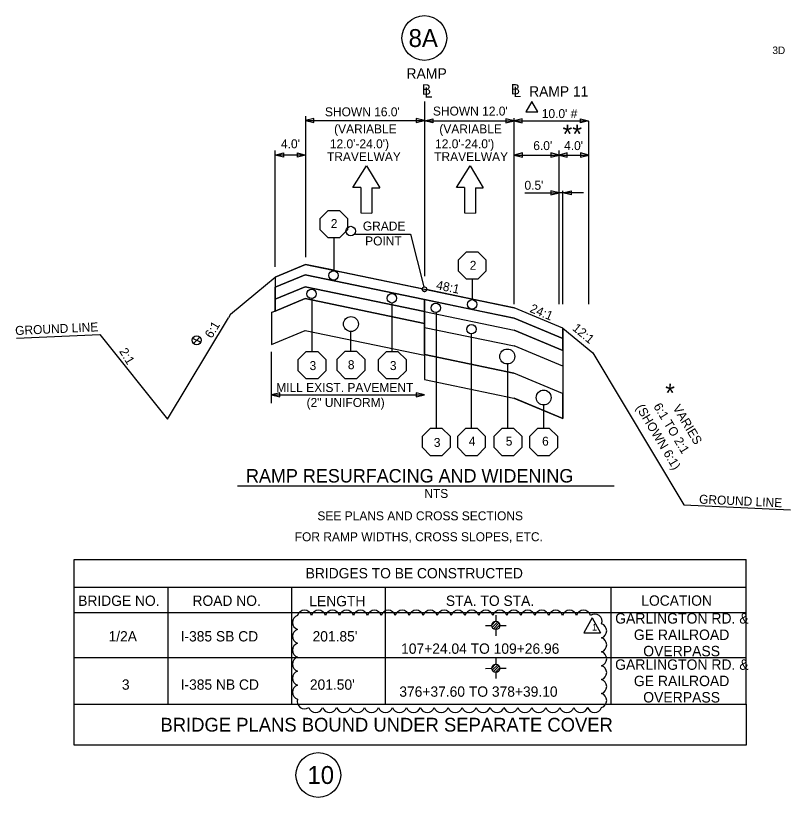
# Model space of a CAD drawing. Extents: x 5017 to 5774, y 4942 to 5266.
# Drawn here: x 5241.9 to 5345.7, y 5114.2 to 5219 of the extents above; entities that cross this region are included whole.
import ezdxf

# ---------------------------------------------------------------- set-up
doc = ezdxf.new("R2010")
doc.units = 0
for name, color, linetype in [('Level 20', 7, 'Continuous'), ('Level 25', 7, 'Continuous'), ('NotForConst', 7, 'Continuous'), ('RD_DDB_EX_Tx', 7, 'Continuous'), ('RD_EX_SU_TX_Misc', 7, 'Continuous'), ('RD_QTY_Intermediate', 7, 'Continuous'), ('RD_QTY_Surf_Course', 7, 'Continuous'), ('RD_SHT_TX', 7, 'Continuous'), ('RD_SHT_Typical', 7, 'Continuous'), ('RD_TX_Misc2', 7, 'Continuous'), ('RD_TX_StaOff', 7, 'Continuous'), ('RD_TX_TypSect', 7, 'Continuous'), ('RD_XS_ExGround', 7, 'Continuous'), ('RD_XS_ExPaveRet', 7, 'Continuous'), ('typical_on', 7, 'Continuous')]:
    doc.layers.add(name, color=color, linetype=linetype)

# ---------------------------------------------------------------- blocks, each defined once
blk = doc.blocks.new('SUE_TFP')
at = {"layer": 'RD_EX_SU_TX_Misc'}
for p, q in [((0, 5.5), (0, 2.22)), ((-2.21, 0.13), (-0.13, 2.21)), ((-1.96, -1.03), (1.03, 1.96)), ((-1.31, -1.79), (1.79, 1.31)), ((-0.3, -2.2), (2.2, 0.3)), ((2.22, 0), (5.53, 0.01)), ((-5.53, -0.01), (-2.22, 0)), ((0, -2.22), (0, -5.5))]:
    blk.add_line(p, q, dxfattribs=at)
blk.add_circle((0, 0), 2.22, dxfattribs=at)

msp = doc.modelspace()

# ---------------------------------------------------------------- linework, layer by layer
at = {"layer": 'Level 20'}
for p, q in [((5287.11, 5195.94), (5288.93, 5198.86)), ((5288.93, 5198.86), (5290.71, 5195.93)), ((5300.99, 5195.94), (5302.81, 5198.86)), ((5302.81, 5198.86), (5304.59, 5195.93)), ((5288.2, 5195.94), (5287.11, 5195.94)), ((5288.2, 5195.94), (5288.2, 5192.54)), ((5289.66, 5195.93), (5290.71, 5195.93)), ((5289.66, 5195.93), (5289.66, 5192.53)), ((5302.08, 5195.94), (5300.99, 5195.94)), ((5302.08, 5195.94), (5302.08, 5192.54)), ((5303.54, 5195.93), (5304.59, 5195.93)), ((5303.54, 5195.93), (5303.54, 5192.53)), ((5288.2, 5192.54), (5289.66, 5192.53)), ((5302.08, 5192.54), (5303.54, 5192.53))]:
    msp.add_line(p, q, dxfattribs=at)
at = {"layer": 'Level 25'}
msp.add_lwpolyline([(5287.46, 5189.7), (5294.82, 5189.7), (5296.63, 5182.62)], dxfattribs=at)
for centre in [(5296.69, 5215.99), (5282.48, 5117.2)]:
    msp.add_circle(centre, 3, dxfattribs=at)
at = {"layer": 'NotForConst'}
for p, q in [((5249.76, 5126.71), (5249.76, 5146.1)), ((5249.76, 5146.1), (5339.84, 5146.1)), ((5339.84, 5126.71), (5339.84, 5146.1)), ((5249.76, 5142.4), (5339.84, 5142.4)), ((5278.92, 5126.71), (5278.92, 5142.4)), ((5291.48, 5126.71), (5291.48, 5142.4)), ((5321.75, 5126.71), (5321.75, 5142.4)), ((5249.76, 5138.97), (5339.84, 5138.97)), ((5249.76, 5132.93), (5339.84, 5132.93))]:
    msp.add_line(p, q, dxfattribs=at)
msp.add_lwpolyline([(5249.76, 5126.71), (5339.84, 5126.71), (5339.84, 5121.18), (5249.76, 5121.18)], close=True, dxfattribs=at)
at = {"layer": 'RD_DDB_EX_Tx'}
for p, q in [((5308.68, 5171.06), (5296.71, 5173.55)), ((5315.22, 5168.33), (5308.68, 5171.06)), ((5296.71, 5170.22), (5308.68, 5167.72)), ((5315.25, 5164.99), (5315.25, 5168.33)), ((5308.68, 5167.72), (5315.25, 5164.99))]:
    msp.add_line(p, q, dxfattribs=at)
for points in [[(5296.71, 5173.55), (5296.71, 5171.35), (5296.71, 5170.22)], [(5315.25, 5168.33), (5315.22, 5168.33)]]:
    msp.add_lwpolyline(points, dxfattribs=at)
msp.add_circle((5312.68, 5167.8), 1, dxfattribs=at)
at = {"layer": 'RD_QTY_Intermediate'}
for p, q in [((5280.73, 5184.26), (5276.71, 5182.58)), ((5296.71, 5180.93), (5280.73, 5184.26)), ((5276.71, 5180.98), (5280.73, 5182.66)), ((5280.73, 5182.66), (5276.71, 5180.98)), ((5276.71, 5182.58), (5276.71, 5180.98)), ((5280.73, 5182.66), (5296.71, 5179.33)), ((5296.71, 5179.33), (5280.73, 5182.66)), ((5276.71, 5179.39), (5280.73, 5181.06)), ((5276.71, 5180.98), (5276.71, 5179.39)), ((5280.73, 5181.06), (5296.71, 5177.74)), ((5296.71, 5180.93), (5296.71, 5179.33)), ((5296.71, 5179.33), (5296.71, 5180.93)), ((5296.71, 5179.33), (5308.71, 5176.83)), ((5296.71, 5177.74), (5296.71, 5179.33)), ((5315.23, 5175.71), (5308.71, 5178.43)), ((5308.71, 5176.83), (5315.23, 5174.11)), ((5315.25, 5174.11), (5315.25, 5175.71))]:
    msp.add_line(p, q, dxfattribs=at)
for points in [[(5308.71, 5178.43), (5303.07, 5179.6), (5296.71, 5180.93)], [(5315.25, 5175.71), (5315.23, 5175.71)], [(5315.23, 5174.11), (5315.25, 5174.11)]]:
    msp.add_lwpolyline(points, dxfattribs=at)
at = {"layer": 'RD_QTY_Surf_Course'}
for p, q in [((5280.77, 5185.64), (5276.71, 5183.95)), ((5284.55, 5184.86), (5280.77, 5185.64)), ((5276.71, 5182.58), (5280.73, 5184.26)), ((5280.73, 5184.26), (5296.71, 5180.93)), ((5284.55, 5184.79), (5284.55, 5184.86)), ((5296.41, 5182.39), (5284.56, 5184.85)), ((5276.71, 5183.95), (5276.71, 5182.58)), ((5303.1, 5180.99), (5297, 5182.26)), ((5296.71, 5180.93), (5308.71, 5178.43)), ((5303.1, 5180.92), (5303.1, 5180.99)), ((5308.71, 5179.82), (5303.12, 5180.99)), ((5315.25, 5177.1), (5308.71, 5179.82)), ((5308.71, 5178.43), (5315.23, 5175.71)), ((5315.25, 5175.71), (5315.25, 5177.1))]:
    msp.add_line(p, q, dxfattribs=at)
for points in [[(5284.56, 5184.85), (5284.55, 5184.79)], [(5303.12, 5180.99), (5303.1, 5180.92)], [(5315.23, 5175.71), (5315.25, 5175.71)]]:
    msp.add_lwpolyline(points, dxfattribs=at)
for centre in [(5284.53, 5184.17), (5303.09, 5180.29)]:
    msp.add_circle(centre, 0.63, dxfattribs=at)
msp.add_arc((5296.71, 5182.32), 0.3, 168.2319, 348.2319, dxfattribs=at)
at = {"layer": 'RD_SHT_TX'}
for p, q in [((5319.18, 5138.27), (5318.05, 5136.24)), ((5319.18, 5138.27), (5320.32, 5136.24)), ((5318.05, 5136.24), (5320.32, 5136.24))]:
    msp.add_line(p, q, dxfattribs=at)
for centre, start, end in [((5280.64, 5138.3), 17.5, 162.5), ((5282.51, 5138.3), 17.5, 162.5), ((5284.38, 5138.3), 17.5, 162.5), ((5286.25, 5138.3), 17.5, 162.5), ((5288.12, 5138.3), 17.5, 162.5), ((5289.99, 5138.3), 17.5, 162.5), ((5291.86, 5138.3), 17.5, 162.5), ((5293.73, 5138.3), 17.5, 162.5), ((5295.6, 5138.3), 17.5, 162.5), ((5297.47, 5138.3), 17.5, 162.5), ((5299.34, 5138.3), 17.5, 162.5), ((5301.2, 5138.3), 17.5, 162.5), ((5303.07, 5138.3), 17.5, 162.5), ((5304.94, 5138.3), 17.5, 162.5), ((5306.81, 5138.3), 17.5, 162.5), ((5308.68, 5138.3), 17.5, 162.5), ((5310.55, 5138.3), 17.5, 162.5), ((5312.42, 5138.3), 17.5, 162.5), ((5314.29, 5138.3), 17.5, 162.5), ((5316.16, 5138.3), 17.5, 162.5), ((5318.03, 5138.3), 17.5, 162.5), ((5280, 5137.66), 107.5, 252.5), ((5319.53, 5137.79), 340.297, 125.297), ((5320.15, 5136.53), 287.5, 72.5), ((5280, 5135.79), 107.5, 252.5), ((5280, 5133.92), 107.5, 252.5), ((5320.15, 5134.66), 287.5, 72.5), ((5320.15, 5132.79), 287.5, 72.5), ((5280, 5132.05), 107.5, 252.5), ((5320.15, 5130.92), 287.5, 72.5), ((5280, 5130.18), 107.5, 252.5), ((5320.15, 5129.05), 287.5, 72.5), ((5280, 5128.31), 107.5, 252.5), ((5320.15, 5127.18), 287.5, 72.5), ((5280.63, 5127.05), 160.297, 305.297), ((5282.13, 5126.54), 197.5, 342.5), ((5284, 5126.54), 197.5, 342.5), ((5285.87, 5126.54), 197.5, 342.5), ((5287.74, 5126.54), 197.5, 342.5), ((5289.61, 5126.54), 197.5, 342.5), ((5291.48, 5126.54), 197.5, 342.5), ((5293.35, 5126.54), 197.5, 342.5), ((5295.22, 5126.54), 197.5, 342.5), ((5297.09, 5126.54), 197.5, 342.5), ((5298.95, 5126.54), 197.5, 342.5), ((5300.82, 5126.54), 197.5, 342.5), ((5302.69, 5126.54), 197.5, 342.5), ((5304.56, 5126.54), 197.5, 342.5), ((5306.43, 5126.54), 197.5, 342.5), ((5308.3, 5126.54), 197.5, 342.5), ((5310.17, 5126.54), 197.5, 342.5), ((5312.04, 5126.54), 197.5, 342.5), ((5313.91, 5126.54), 197.5, 342.5), ((5315.78, 5126.54), 197.5, 342.5), ((5317.65, 5126.54), 197.5, 342.5), ((5319.51, 5126.54), 197.5, 342.5)]:
    msp.add_arc(centre, 0.98, start, end, dxfattribs=at)
at = {"layer": 'RD_SHT_Typical'}
for p, q in [((5276.71, 5183.95), (5280.77, 5185.64)), ((5276.71, 5182.58), (5280.73, 5184.26)), ((5276.71, 5183.95), (5276.71, 5182.58)), ((5276.71, 5180.98), (5280.73, 5182.66)), ((5276.71, 5180.98), (5276.71, 5182.58)), ((5276.21, 5179.18), (5280.73, 5181.06)), ((5276.71, 5179.39), (5276.71, 5180.98)), ((5315.25, 5177.1), (5308.71, 5179.82)), ((5276.21, 5179.18), (5276.21, 5174.92)), ((5296.71, 5179.33), (5296.71, 5177.74)), ((5296.71, 5177.74), (5296.71, 5176.36)), ((5296.71, 5173.55), (5296.71, 5177.74)), ((5315.23, 5175.71), (5308.71, 5178.43)), ((5276.21, 5174.92), (5280.73, 5176.8)), ((5315.23, 5174.11), (5308.71, 5176.83)), ((5315.25, 5177.1), (5319.25, 5173.77)), ((5315.25, 5177.1), (5315.25, 5164.99)), ((5296.71, 5176.36), (5296.71, 5173.48)), ((5315.23, 5172), (5308.71, 5174.71)), ((5296.71, 5173.55), (5296.71, 5170.22)), ((5319.25, 5173.77), (5331.47, 5153.4)), ((5315.22, 5168.33), (5308.68, 5171.06)), ((5315.25, 5164.99), (5308.71, 5167.72))]:
    msp.add_line(p, q, dxfattribs=at)
for points in [[(5280.77, 5185.64), (5296.71, 5182.32)], [(5280.73, 5184.26), (5296.71, 5180.93)], [(5280.73, 5182.66), (5296.71, 5179.33)], [(5296.71, 5182.32), (5308.71, 5179.82)], [(5280.73, 5181.06), (5296.71, 5177.74)], [(5296.71, 5180.93), (5308.71, 5178.43)], [(5296.71, 5179.33), (5308.71, 5176.83)], [(5280.73, 5176.8), (5296.71, 5173.48)], [(5296.71, 5177.21), (5308.71, 5174.71)], [(5296.71, 5173.55), (5308.68, 5171.06)], [(5296.71, 5170.22), (5308.68, 5167.72)]]:
    msp.add_lwpolyline(points, dxfattribs=at)
at = {"layer": 'RD_TX_StaOff'}
msp.add_line((5262.31, 5142.4), (5262.31, 5126.71), dxfattribs=at)
at = {"layer": 'RD_TX_TypSect'}
for p, q in [((5296.7, 5207.49), (5296.7, 5184.08)), ((5280.77, 5205.52), (5280.77, 5186.62)), ((5308.71, 5180.31), (5308.71, 5205.24)), ((5280.77, 5204.93), (5296.71, 5204.93)), ((5296.71, 5204.9), (5308.71, 5204.9)), ((5308.71, 5204.9), (5318.71, 5204.9)), ((5318.75, 5180.31), (5318.75, 5204.83)), ((5276.71, 5185.31), (5276.71, 5200.92)), ((5314.75, 5180.31), (5314.75, 5200.92)), ((5280.77, 5200.3), (5276.71, 5200.3)), ((5308.75, 5200.3), (5314.75, 5200.3)), ((5314.75, 5200.3), (5318.75, 5200.3)), ((5310.16, 5195.23), (5314.75, 5195.23)), ((5318.01, 5195.23), (5314.75, 5195.23)), ((5315.25, 5180.31), (5315.25, 5195.5)), ((5284.55, 5189.19), (5284.55, 5184.79)), ((5303.1, 5183.65), (5303.1, 5180.92)), ((5281.65, 5173.99), (5281.65, 5181.06)), ((5292.4, 5173.99), (5292.4, 5180.47)), ((5298.3, 5163.69), (5298.3, 5179.27)), ((5265.64, 5175.74), (5266.72, 5175.2)), ((5265.77, 5175.05), (5266.59, 5175.9)), ((5286.85, 5174.02), (5286.85, 5176.65)), ((5303.02, 5163.69), (5303.02, 5176.35)), ((5276.21, 5167.03), (5276.21, 5173.91)), ((5307.9, 5163.69), (5307.9, 5172.32)), ((5312.69, 5163.69), (5312.69, 5166.8)), ((5271.64, 5155.95), (5322.14, 5155.95))]:
    msp.add_line(p, q, dxfattribs=at)
for points in [[(5311.09, 5207.48), (5310.29, 5206.09), (5311.89, 5206.09)], [(5281.87, 5204.65), (5281.87, 5205.2), (5280.77, 5204.93)], [(5295.6, 5205.2), (5295.6, 5204.65), (5296.71, 5204.93)], [(5297.81, 5205.17), (5297.81, 5204.62), (5296.71, 5204.9)], [(5307.61, 5205.17), (5307.61, 5204.62), (5308.71, 5204.9)], [(5309.81, 5204.62), (5309.81, 5205.17), (5308.71, 5204.9)], [(5317.6, 5204.62), (5317.6, 5205.17), (5318.71, 5204.9)], [(5277.82, 5200.58), (5277.82, 5200.03), (5276.71, 5200.3)], [(5279.67, 5200.03), (5279.67, 5200.58), (5280.77, 5200.3)], [(5309.85, 5200.03), (5309.85, 5200.58), (5308.75, 5200.3)], [(5313.64, 5200.58), (5313.64, 5200.03), (5314.75, 5200.3)], [(5315.85, 5200.03), (5315.85, 5200.58), (5314.75, 5200.3)], [(5317.64, 5200.58), (5317.64, 5200.03), (5318.75, 5200.3)], [(5313.64, 5195.5), (5313.64, 5194.95), (5314.75, 5195.23)], [(5316.35, 5195.5), (5316.35, 5194.95), (5315.25, 5195.23)], [(5277.32, 5167.88), (5277.32, 5168.43), (5276.21, 5168.15)], [(5295.6, 5168.43), (5295.6, 5167.88), (5296.71, 5168.15)]]:
    msp.add_lwpolyline(points, close=True, dxfattribs=at)
for centre, radius in [((5286.82, 5190.12), 0.63), ((5284.53, 5184.17), 0.63), ((5281.58, 5181.69), 0.63), ((5296.71, 5182.32), 0.3), ((5292.34, 5181.1), 0.63), ((5303.09, 5180.29), 0.63), ((5298.23, 5179.82), 0.63), ((5286.85, 5177.65), 1), ((5303, 5176.96), 0.63), ((5266.18, 5175.48), 0.6), ((5307.8, 5173.3), 1), ((5312.68, 5167.8), 1)]:
    msp.add_circle(centre, radius, dxfattribs=at)
at = {"layer": 'RD_XS_ExGround'}
for p, q in [((5274.11, 5181.78), (5276.71, 5183.95)), ((5270.72, 5178.96), (5274.11, 5181.78)), ((5270.72, 5178.96), (5270.45, 5178.47)), ((5262.28, 5164.9), (5270.45, 5178.47)), ((5242.05, 5175.75), (5253.2, 5176.25)), ((5253.2, 5176.25), (5262.28, 5164.9)), ((5276.21, 5168.15), (5296.71, 5168.15)), ((5331.47, 5153.4), (5345.74, 5152.75))]:
    msp.add_line(p, q, dxfattribs=at)
at = {"layer": 'RD_XS_ExPaveRet'}
for p, q in [((5296.71, 5177.74), (5280.73, 5181.06)), ((5276.21, 5179.18), (5276.21, 5174.92)), ((5296.71, 5177.51), (5296.71, 5177.74)), ((5276.21, 5174.92), (5280.73, 5176.8)), ((5280.73, 5176.8), (5296.71, 5173.48))]:
    msp.add_line(p, q, dxfattribs=at)
for points in [[(5280.73, 5181.06), (5276.71, 5179.39), (5276.21, 5179.18)], [(5296.71, 5173.48), (5296.71, 5175.92), (5296.71, 5177.51)]]:
    msp.add_lwpolyline(points, dxfattribs=at)
at = {"layer": 'typical_on'}
for points in [[(5286.4, 5191.8), (5286.4, 5190.27), (5285.32, 5189.19), (5283.79, 5189.19), (5282.71, 5190.27), (5282.71, 5191.8), (5283.79, 5192.88), (5285.32, 5192.88)], [(5304.95, 5186.26), (5304.95, 5184.73), (5303.87, 5183.65), (5302.34, 5183.65), (5301.26, 5184.73), (5301.26, 5186.26), (5302.34, 5187.34), (5303.87, 5187.34)], [(5283.49, 5172.9), (5283.49, 5171.37), (5282.4, 5170.29), (5280.87, 5170.29), (5279.79, 5171.37), (5279.79, 5172.9), (5280.87, 5173.98), (5282.4, 5173.98)], [(5288.7, 5172.94), (5288.7, 5171.41), (5287.62, 5170.32), (5286.09, 5170.32), (5285, 5171.41), (5285, 5172.94), (5286.09, 5174.02), (5287.62, 5174.02)], [(5294.24, 5172.9), (5294.24, 5171.37), (5293.16, 5170.29), (5291.63, 5170.29), (5290.55, 5171.37), (5290.55, 5172.9), (5291.63, 5173.98), (5293.16, 5173.98)], [(5300.13, 5162.61), (5300.13, 5161.08), (5299.05, 5160), (5297.52, 5160), (5296.44, 5161.08), (5296.44, 5162.61), (5297.52, 5163.69), (5299.05, 5163.69)], [(5304.86, 5162.61), (5304.86, 5161.08), (5303.77, 5160), (5302.24, 5160), (5301.16, 5161.08), (5301.16, 5162.61), (5302.24, 5163.69), (5303.77, 5163.69)], [(5309.74, 5162.61), (5309.74, 5161.08), (5308.66, 5160), (5307.13, 5160), (5306.05, 5161.08), (5306.05, 5162.61), (5307.13, 5163.69), (5308.66, 5163.69)], [(5314.52, 5162.6), (5314.52, 5161.07), (5313.44, 5159.99), (5311.91, 5159.99), (5310.83, 5161.07), (5310.83, 5162.6), (5311.91, 5163.68), (5313.44, 5163.68)]]:
    msp.add_lwpolyline(points, close=True, dxfattribs=at)

# ---------------------------------------------------------------- block references
at = {"layer": 'NotForConst', "xscale": 0.24999999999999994, "yscale": 0.24999999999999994}
for p in [(5306.27, 5137.25), (5306.27, 5131.5)]:
    msp.add_blockref('SUE_TFP', p, dxfattribs=at)

# ---------------------------------------------------------------- texts
at = {"layer": 'Level 25'}
for s, height, p in [('8A', 2.4, (5294.58, 5214.79)), ('RAMP', 1.4, (5294.29, 5210.53)), ('B ', 1.4, (5296.34, 5208.39)), ('GRADE', 1.2, (5288.45, 5190.19)), ('POINT', 1.2, (5288.76, 5188.19)), ('10', 2.4, (5281.02, 5116))]:
    msp.add_text(s, height=height, dxfattribs=at).set_placement(p)
at = {"layer": 'NotForConst'}
for s, height, p in [('BRIDGES TO BE CONSTRUCTED', 1.3845, (5280.79, 5143.56)), ('BRIDGE NO.', 1.384, (5250.3, 5139.87)), ('ROAD NO.', 1.384, (5265.62, 5139.87)), ('LENGTH', 1.384, (5281.28, 5139.82)), ('STA. TO STA.', 1.3845, (5299.58, 5139.87)), ('LOCATION', 1.384, (5325.77, 5139.89)), ('GARLINGTON RD. & ', 1.4, (5322.26, 5137.5)), ('1/2A', 1.384, (5254.37, 5135.1)), ('I-385 SB CD', 1.3845, (5264.03, 5135.1)), ("201.85'", 1.384, (5281.71, 5135.1)), ('GE RAILROAD', 1.4, (5324.77, 5135.3)), ('107+24.04 TO 109+26.96', 1.3845, (5293.58, 5133.45)), ('OVERPASS', 1.4, (5326.02, 5133.11)), ('GARLINGTON RD. & ', 1.4, (5322.26, 5131.3)), ('3', 1.38, (5256.16, 5128.63)), ('I-385 NB CD', 1.3845, (5264.03, 5128.63)), ("201.50'", 1.384, (5281.35, 5128.63)), ('GE RAILROAD', 1.4, (5324.77, 5129.11)), ('376+37.60 TO 378+39.10', 1.3845, (5293.34, 5127.69)), ('OVERPASS', 1.4, (5326.02, 5126.92)), ('BRIDGE PLANS BOUND UNDER SEPARATE COVER', 1.846, (5261.33, 5123.02))]:
    msp.add_text(s, height=height, dxfattribs=at).set_placement(p)
at = {"layer": 'RD_SHT_TX'}
msp.add_text('1', height=0.88, dxfattribs=at).set_placement((5319.18, 5136.57))
at = {"layer": 'RD_TX_Misc2'}
msp.add_text('3D', height=1, dxfattribs=at).set_placement((5343.34, 5213.85))
at = {"layer": 'RD_TX_TypSect'}
for s, height, p in [('L', 1.4, (5296.73, 5208)), ('B', 1.38, (5308.28, 5208.43)), ('L', 1.4, (5308.63, 5208.08)), ('RAMP 11', 1.384, (5310.74, 5208.14)), ("SHOWN 16.0'", 1.2, (5283.37, 5205.5)), ("SHOWN 12.0'", 1.2, (5297.84, 5205.6)), ("10.0' #", 1.2, (5312.43, 5205.26)), ('(VARIABLE', 1.2, (5284.6, 5203.21)), ('(VARIABLE', 1.2, (5298.7, 5203.21)), ('**', 2.5, (5315.22, 5201.88)), ("4.0'", 1.2, (5277.48, 5201.21)), ("12.0'-24.0')", 1.2, (5284.03, 5201.21)), ("12.0'-24.0')", 1.2, (5298.13, 5201.21)), ("6.0'", 1.2, (5311.29, 5200.97)), ("4.0'", 1.2, (5315.42, 5200.97)), ('TRAVELWAY', 1.2, (5283.64, 5199.49)), ('TRAVELWAY', 1.2, (5298.01, 5199.49)), ("0.5'", 1.2, (5310.11, 5195.65)), ('2', 1.2, (5284.15, 5190.52)), ('2', 1.2, (5302.77, 5184.92)), ('3', 1.2, (5281.31, 5171.48)), ('8', 1.2, (5286.44, 5171.6)), ('3', 1.2, (5292.07, 5171.48)), ('MILL EXIST. PAVEMENT', 1.2, (5276.84, 5168.54)), ('*', 2.5, (5328.97, 5167.16)), ('(2" UNIFORM)', 1.2, (5280.91, 5166.54)), ('3', 1.2, (5297.96, 5161.18)), ('4', 1.2, (5302.65, 5161.35)), ('5', 1.2, (5307.6, 5161.35)), ('6', 1.2, (5312.47, 5161.35)), ('RAMP RESURFACING AND WIDENING', 1.8, (5272.79, 5156.41)), ('NTS', 1.2, (5296.68, 5154.34)), ('SEE PLANS AND CROSS SECTIONS', 1.2, (5282.36, 5151.34)), ('FOR RAMP WIDTHS, CROSS SLOPES, ETC.', 1.2, (5279.32, 5148.54))]:
    msp.add_text(s, height=height, dxfattribs=at).set_placement(p)
for s, rotation, p in [('48:1', 348.2317, (5298.21, 5182.34)), ('24:1', 337.3801, (5310.73, 5179.3)), ('GROUND LINE', 2.6095, (5241.88, 5176.17)), ('6:1', 59.0362, (5268.21, 5175.64)), ('12:1', 320.1939, (5316.44, 5176.93)), ('2:1', 300.9638, (5255.76, 5174.01)), ('(SHOWN 6:1)', 300.9638, (5325, 5166.47)), ('6:1 TO 2:1', 300.9638, (5327.35, 5166.63)), ('VARIES', 300.9638, (5329.93, 5166.41)), ('GROUND LINE', 357.3905, (5333.49, 5153.59))]:
    msp.add_text(s, height=1.2, rotation=rotation, dxfattribs=at).set_placement(p)

doc.saveas('drawing.dxf')
